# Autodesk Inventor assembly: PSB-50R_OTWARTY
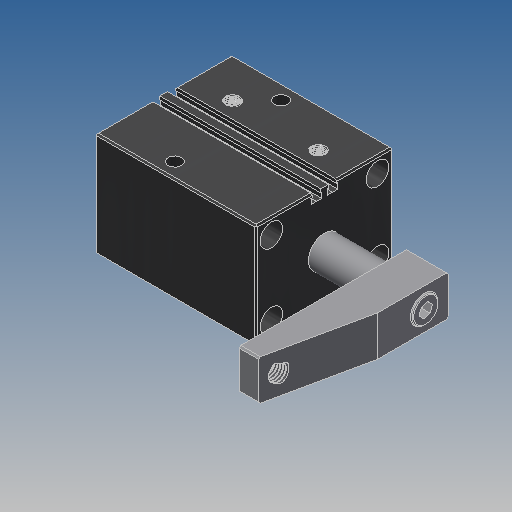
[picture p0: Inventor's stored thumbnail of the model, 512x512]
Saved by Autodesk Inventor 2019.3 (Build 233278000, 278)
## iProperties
Created: 2010-02
Part Number: PSB-50R_OTWARTY
Material: Ogólny
Document SubType Name: Assembly
Designer: CADENGINEERING4
Sending System: PRO/ENGINEER BY PARAMETRIC TECHNOLOGY CORPORATION, 2007170
Preprocessor: PRO/ENGINEER BY PARAMETRIC TECHNOLOGY CORPORATION, 2007170
Title: PSB-50_ASM
Author: Administrator
Revision Number: 1LAST_VERSION
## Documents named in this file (6)
- E:\SERWER_ZAPAS\Pneumatic\PSB PNEUMATIC SWING\PSB-50\PSB-50R_OTWARTY.iam
- E:\SERWER_ZAPAS\Pneumatic\PSB PNEUMATIC SWING\PSB-50\PSB-50BT.ipt
- E:\SERWER_ZAPAS\Pneumatic\PSB PNEUMATIC SWING\PSB-50\PSB-50HSG.ipt
- E:\SERWER_ZAPAS\Pneumatic\PSB PNEUMATIC SWING\PSB-50\PSB-50HG.ipt
- E:\SERWER_ZAPAS\Pneumatic\PSB PNEUMATIC SWING\PSB-50\PSB-50YB.ipt
- E:\SERWER_ZAPAS\Pneumatic\PSB PNEUMATIC SWING\PSB-50\M10LC.ipt
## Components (5 placed, 5 different names)
1. PSB-50BT_0 — Zestawiające:6, Kątowe:1, Zestawiające:7
2. PSB-50HSG_1 — Zestawiające:1, Zestawiające:4, Zestawiające:6, Zestawiające:7
3. PSB-50HG_2
4. PSB-50YB_3 — Zestawiające:1, Zestawiające:2, Zestawiające:4, Zestawiające:5, Kątowe:1
5. M10LC_4 — Zestawiające:2, Zestawiające:5
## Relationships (7: Mate 6, Angle 1)
- Zestawiające:1 [Mate]: PSB-50HSG_1 ↔ PSB-50YB_3
- Zestawiające:2 [Mate]: PSB-50YB_3 ↔ M10LC_4
- Zestawiające:4 [Mate]: PSB-50HSG_1 ↔ PSB-50YB_3
- Zestawiające:5 [Mate]: PSB-50YB_3 ↔ M10LC_4
- Zestawiające:6 [Mate]: PSB-50BT_0 ↔ PSB-50HSG_1
- Kątowe:1 [Angle]: PSB-50BT_0 ↔ PSB-50YB_3
- Zestawiające:7 [Mate]: PSB-50BT_0 ↔ PSB-50HSG_1
